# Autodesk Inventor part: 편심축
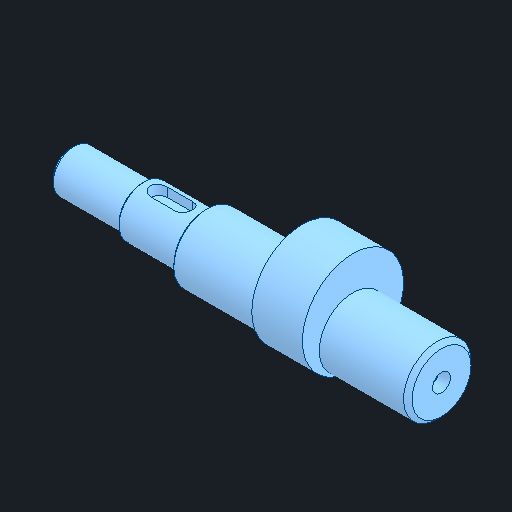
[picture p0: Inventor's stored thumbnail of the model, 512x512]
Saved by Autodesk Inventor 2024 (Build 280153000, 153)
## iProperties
Created: 2025-02
Part Number: 편심축
Material: 강철, 탄소
Document SubType Name: Modeling
Designer: kh_501
Density: 7.85 g/cm^3
Appearance: 기본값
Author: jhkim
Sending System: Autodesk Inventor 2025
Preprocessor: ST-DEVELOPER v20
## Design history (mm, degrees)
node "편심축1"
node "솔리드2"
node "솔리드1"
